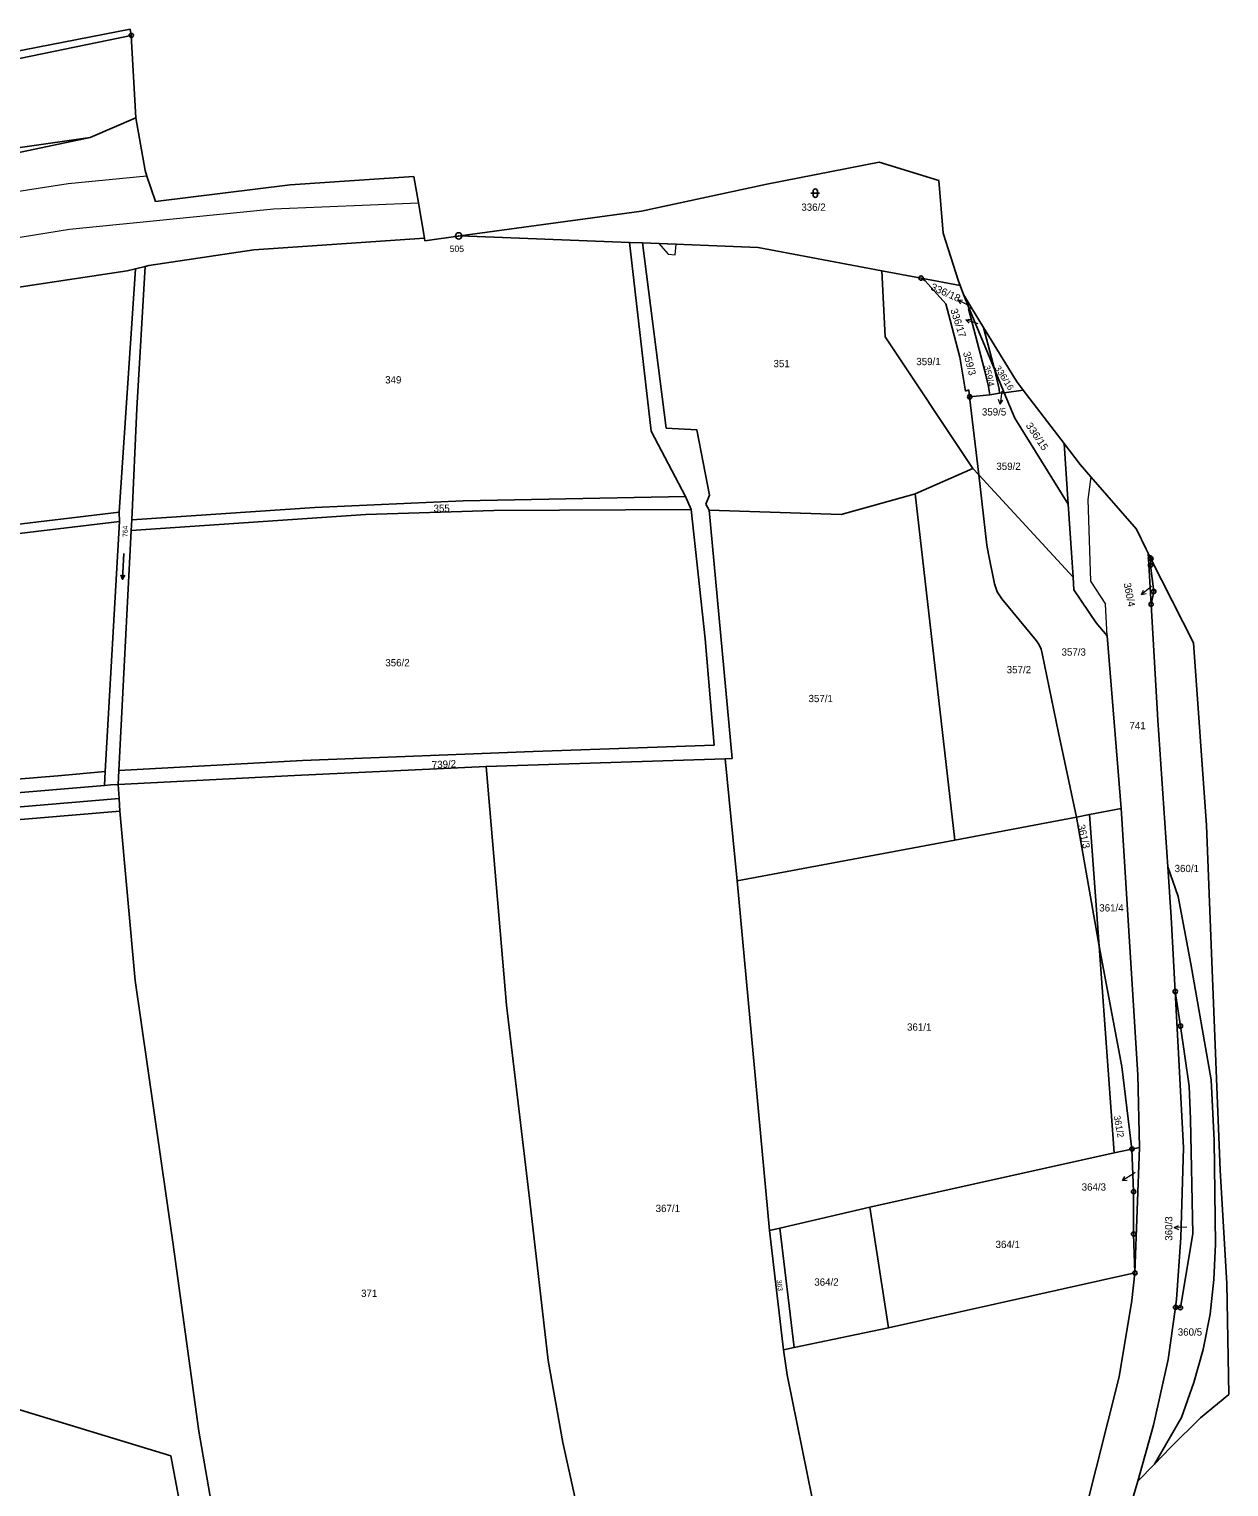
# Model space of a CAD drawing. Extents: x -701211 to -698780, y -1014269 to -1012378.
# Drawn here: x -699060.5 to -698780.2, y -1012938.4 to -1012597.8 of the extents above; entities that cross this region are included whole.
import ezdxf
from ezdxf.enums import TextEntityAlignment as Align

# ---------------------------------------------------------------- set-up
doc = ezdxf.new("R2010")
doc.units = 0
doc.header["$LTSCALE"] = 0.68
for name, color, linetype, lineweight in [('1', 7, 'Continuous', 25), ('13', 7, 'Continuous', 13), ('3', 7, 'Continuous', 25), ('4', 7, 'Continuous', 13), ('7', 7, 'Continuous', 13), ('8', 7, 'Continuous', 25)]:
    doc.layers.add(name, color=color, linetype=linetype, lineweight=lineweight)
doc.layers.add('2', color=7, linetype='Continuous')

msp = doc.modelspace()

# ---------------------------------------------------------------- linework, layer by layer
at = {"layer": '1'}
for p, q in [((-699126.02, -1012615.12), (-699036.85, -1012597.77)), ((-699036.85, -1012597.77), (-699036.63, -1012599.25)), ((-699081.26, -1012608.48), (-699036.63, -1012599.25)), ((-699036.63, -1012599.25), (-699035.57, -1012618.46)), ((-699046.25, -1012623.07), (-699035.57, -1012618.46)), ((-699035.57, -1012618.46), (-699033.39, -1012630.77)), ((-699046.25, -1012623.07), (-699081.97, -1012630.68)), ((-699046.25, -1012623.07), (-699072.26, -1012626.78)), ((-698888.11, -1012634.01), (-698861.89, -1012628.84)), ((-698861.89, -1012628.84), (-698847.93, -1012633.13)), ((-699033.39, -1012630.77), (-699032.95, -1012632.09)), ((-699032.95, -1012632.09), (-699030.95, -1012638.01)), ((-698999.49, -1012634.17), (-698970.61, -1012632.17)), ((-698969.55, -1012638.33), (-698970.61, -1012632.17)), ((-699030.95, -1012638.01), (-698999.49, -1012634.17)), ((-698917.43, -1012640.29), (-698888.11, -1012634.01)), ((-698847.93, -1012633.13), (-698846.97, -1012645.46)), ((-698968.12, -1012646.63), (-698969.55, -1012638.33)), ((-698843.38, -1012656.67), (-698846.97, -1012645.46)), ((-699032.52, -1012653), (-699008.02, -1012649.3)), ((-699008.02, -1012649.3), (-698968.12, -1012646.63)), ((-698968.02, -1012647.24), (-698968.12, -1012646.63)), ((-698959.75, -1012646.1), (-698920.25, -1012647.62)), ((-698920.25, -1012647.62), (-698917.16, -1012647.74)), ((-698915.17, -1012691.68), (-698920.25, -1012647.62)), ((-698917.16, -1012647.74), (-698890.19, -1012648.78)), ((-698911.66, -1012690.99), (-698917.16, -1012647.74)), ((-698890.19, -1012648.78), (-698861.31, -1012654.22)), ((-699092.82, -1012662.56), (-699037.6, -1012654.23)), ((-699039.44, -1012710.64), (-699035.62, -1012653.75)), ((-699037.6, -1012654.23), (-699035.62, -1012653.75)), ((-699035.62, -1012653.75), (-699033.39, -1012653.21)), ((-699035.36, -1012686.4), (-699033.39, -1012653.21)), ((-699033.39, -1012653.21), (-699032.52, -1012653)), ((-698861.31, -1012654.22), (-698852.1, -1012655.95)), ((-698860.52, -1012669.65), (-698861.31, -1012654.22)), ((-698852.1, -1012655.95), (-698851.13, -1012656.61)), ((-698852.1, -1012655.95), (-698843.01, -1012657.66)), ((-698851.13, -1012656.61), (-698846.34, -1012661.96)), ((-698843.38, -1012656.67), (-698843.01, -1012657.66)), ((-698843.01, -1012657.66), (-698842.23, -1012659.77)), ((-698846.34, -1012661.96), (-698845.32, -1012665.77)), ((-698842.23, -1012659.77), (-698840.32, -1012662.89)), ((-698840.87, -1012663.04), (-698842.23, -1012659.77)), ((-698840.87, -1012663.04), (-698840.32, -1012662.89)), ((-698834.96, -1012677.21), (-698840.87, -1012663.04)), ((-698840.32, -1012662.89), (-698837.52, -1012667.45)), ((-698845.32, -1012665.77), (-698843.08, -1012674.41)), ((-698839.98, -1012700.42), (-698860.52, -1012669.65)), ((-698834.96, -1012677.21), (-698837.52, -1012667.45)), ((-698837.52, -1012667.45), (-698829.82, -1012680.02)), ((-698843.08, -1012674.41), (-698841.72, -1012682.4)), ((-698832.67, -1012682.72), (-698834.96, -1012677.21)), ((-698829.82, -1012680.02), (-698828.22, -1012682.11)), ((-698841.72, -1012682.4), (-698840.95, -1012682.06)), ((-698840.95, -1012682.06), (-698840.76, -1012683.69)), ((-698836.05, -1012683.26), (-698840.76, -1012683.69)), ((-698836.05, -1012683.26), (-698833.75, -1012682.87)), ((-698833.75, -1012682.87), (-698832.67, -1012682.72)), ((-698832.67, -1012682.72), (-698828.22, -1012682.11)), ((-698830.2, -1012688.64), (-698832.67, -1012682.72)), ((-698818.69, -1012694.57), (-698828.22, -1012682.11)), ((-699036.52, -1012712.46), (-699035.36, -1012686.4)), ((-698840.76, -1012683.69), (-698838.64, -1012701.88)), ((-698830.2, -1012688.64), (-698817.74, -1012708.79)), ((-698915.17, -1012691.68), (-698907.14, -1012706.97)), ((-698911.66, -1012690.99), (-698904.48, -1012691.44)), ((-698904.48, -1012691.44), (-698901.52, -1012706.7)), ((-698814.91, -1012699.52), (-698818.69, -1012694.57)), ((-698818.69, -1012694.57), (-698817.74, -1012708.79)), ((-698853.48, -1012706.34), (-698839.98, -1012700.42)), ((-698839.98, -1012700.42), (-698838.64, -1012701.88)), ((-698812.44, -1012702.35), (-698814.91, -1012699.52)), ((-698838.64, -1012701.88), (-698816.6, -1012725.84)), ((-698838.64, -1012701.88), (-698836.72, -1012718.36)), ((-698801.76, -1012714.59), (-698812.44, -1012702.35)), ((-698907.14, -1012706.97), (-698959.08, -1012707.96)), ((-698907.14, -1012706.97), (-698905.81, -1012709.99)), ((-698901.52, -1012706.7), (-698902.42, -1012708.76)), ((-698870.75, -1012711.19), (-698853.7, -1012706.43)), ((-698853.7, -1012706.43), (-698853.48, -1012706.34)), ((-698844.23, -1012787.25), (-698853.48, -1012706.34)), ((-699039.44, -1012710.64), (-699104.93, -1012718.54)), ((-699039.4, -1012712.83), (-699039.44, -1012710.64)), ((-699036.52, -1012712.46), (-698993.76, -1012709.53)), ((-698993.76, -1012709.53), (-698959.08, -1012707.96)), ((-698951.92, -1012710.26), (-698981.79, -1012711.16)), ((-698905.81, -1012709.99), (-698951.92, -1012710.26)), ((-698905.81, -1012709.99), (-698902.58, -1012740.24)), ((-698902.42, -1012708.76), (-698901.65, -1012710.16)), ((-698901.65, -1012710.16), (-698870.75, -1012711.19)), ((-698896.26, -1012768.22), (-698901.65, -1012710.16)), ((-698817.74, -1012708.79), (-698816.6, -1012725.84)), ((-699039.4, -1012712.83), (-699113.18, -1012721.68)), ((-699039.4, -1012712.83), (-699042.73, -1012771.27)), ((-698981.79, -1012711.16), (-699036.63, -1012714.92)), ((-699036.63, -1012714.92), (-699036.52, -1012712.46)), ((-699036.63, -1012714.92), (-699039.53, -1012771.03)), ((-698799.5, -1012719.32), (-698801.76, -1012714.59)), ((-698836.72, -1012718.36), (-698836.39, -1012720.45)), ((-698836.39, -1012720.45), (-698834.96, -1012727.42)), ((-698799.5, -1012719.32), (-698799.05, -1012720.26)), ((-698798.53, -1012721.32), (-698799.05, -1012720.26)), ((-698798.36, -1012732.18), (-698799.05, -1012720.26)), ((-698798.42, -1012721.54), (-698798.54, -1012723.07)), ((-698798.54, -1012723.07), (-698797.74, -1012729.18)), ((-698798.53, -1012721.32), (-698798.42, -1012721.54)), ((-698798.42, -1012721.54), (-698788.46, -1012741.18)), ((-698834.96, -1012727.42), (-698834.33, -1012729.28)), ((-698816.6, -1012725.84), (-698816.4, -1012728.77)), ((-698834.33, -1012729.28), (-698833.28, -1012730.93)), ((-698833.28, -1012730.93), (-698825.18, -1012740.68)), ((-698816.4, -1012728.77), (-698811.18, -1012736.53)), ((-698797.74, -1012729.18), (-698798.36, -1012732.18)), ((-698796.81, -1012759.25), (-698798.36, -1012732.18)), ((-698811.18, -1012736.53), (-698808.65, -1012739.51)), ((-698900.42, -1012765.09), (-698902.58, -1012740.24)), ((-698825.18, -1012740.68), (-698824.54, -1012741.62)), ((-698805.36, -1012779.92), (-698808.65, -1012739.51)), ((-698785.46, -1012783.85), (-698788.46, -1012741.18)), ((-698824.54, -1012741.62), (-698824.08, -1012742.66)), ((-698824.08, -1012742.66), (-698823.8, -1012743.63)), ((-698823.8, -1012743.63), (-698820.02, -1012762.19)), ((-698794.47, -1012793.5), (-698796.81, -1012759.25)), ((-698942.76, -1012766.53), (-698900.42, -1012765.09)), ((-698820.02, -1012762.19), (-698815.81, -1012781.89)), ((-698996.59, -1012768.68), (-698942.76, -1012766.53)), ((-698953.68, -1012770.1), (-698897.88, -1012768.27)), ((-698897.88, -1012768.27), (-698896.26, -1012768.22)), ((-698895.06, -1012796.83), (-698897.88, -1012768.27)), ((-699042.73, -1012771.27), (-699053.75, -1012772.27)), ((-699039.53, -1012771.03), (-699039.7, -1012774.26)), ((-699039.53, -1012771.03), (-698996.59, -1012768.68)), ((-698998.45, -1012772.17), (-698953.68, -1012770.1)), ((-698948.95, -1012825.84), (-698953.68, -1012770.1)), ((-699090.43, -1012778.52), (-699042.9, -1012774.48)), ((-699053.75, -1012772.27), (-699084.52, -1012774.69)), ((-699041.4, -1012774.35), (-699039.7, -1012774.26)), ((-699039.7, -1012774.26), (-698998.45, -1012772.17)), ((-699039.47, -1012777.54), (-699039.7, -1012774.26)), ((-699093.38, -1012782.13), (-699039.47, -1012777.54)), ((-699039.26, -1012780.51), (-699039.47, -1012777.54)), ((-699094.95, -1012785.19), (-699039.26, -1012780.51)), ((-699039.26, -1012780.51), (-699035.71, -1012820.12)), ((-698815.81, -1012781.89), (-698844.23, -1012787.25)), ((-698812.78, -1012781.32), (-698815.81, -1012781.89)), ((-698815.81, -1012781.89), (-698810.53, -1012812.04)), ((-698805.36, -1012779.92), (-698812.78, -1012781.32)), ((-698812.78, -1012781.32), (-698810.53, -1012812.04)), ((-698801.47, -1012842.16), (-698805.36, -1012779.92)), ((-698784.24, -1012813.68), (-698785.46, -1012783.85)), ((-698844.23, -1012787.25), (-698895.06, -1012796.83)), ((-698794.47, -1012793.5), (-698793.66, -1012805.28)), ((-698794.47, -1012793.5), (-698792.08, -1012800.48)), ((-698887.52, -1012878.47), (-698895.06, -1012796.83)), ((-698792.08, -1012800.48), (-698789.1, -1012816.16)), ((-698792.72, -1012822.65), (-698793.66, -1012805.28)), ((-698810.53, -1012812.04), (-698807, -1012860.39)), ((-698789.1, -1012816.16), (-698784.31, -1012843.27)), ((-698784.24, -1012813.68), (-698782.27, -1012864.42)), ((-699035.71, -1012820.12), (-699026.91, -1012881.19)), ((-698792.72, -1012822.65), (-698791.5, -1012830.74)), ((-698791.78, -1012840.01), (-698792.72, -1012822.65)), ((-698943.52, -1012871.68), (-698948.95, -1012825.84)), ((-698790.8, -1012859.21), (-698791.78, -1012840.01)), ((-698801.09, -1012859.08), (-698801.47, -1012842.16)), ((-698784.31, -1012843.27), (-698783.65, -1012857.46)), ((-698789.18, -1012852.51), (-698788.59, -1012879.31)), ((-698807, -1012860.39), (-698864.05, -1012873.08)), ((-698802.86, -1012859.47), (-698807, -1012860.39)), ((-698801.09, -1012859.08), (-698802.86, -1012859.47)), ((-698802.86, -1012859.47), (-698802.46, -1012869.41)), ((-698802.16, -1012888.42), (-698801.09, -1012859.08)), ((-698791.42, -1012880.12), (-698790.8, -1012859.21)), ((-698783.65, -1012857.46), (-698783.32, -1012881.73)), ((-698782.27, -1012864.42), (-698780.68, -1012890.86)), ((-698802.46, -1012869.41), (-698802.47, -1012879.35)), ((-698939.21, -1012908.86), (-698943.52, -1012871.68)), ((-698885.12, -1012877.92), (-698864.05, -1012873.08)), ((-698864.05, -1012873.08), (-698859.75, -1012901.26)), ((-698887.52, -1012878.47), (-698885.12, -1012877.92)), ((-698884.24, -1012906.37), (-698887.52, -1012878.47)), ((-698885.12, -1012877.92), (-698881.79, -1012905.86)), ((-698802.47, -1012879.35), (-698802.16, -1012888.42)), ((-698792.41, -1012894.66), (-698791.42, -1012880.12)), ((-698788.59, -1012879.31), (-698791.52, -1012896.52)), ((-699026.91, -1012881.19), (-699020.81, -1012925.37)), ((-698783.32, -1012881.73), (-698783.72, -1012889.99)), ((-698802.16, -1012888.42), (-698859.75, -1012901.26)), ((-698802.91, -1012894.83), (-698802.16, -1012888.42)), ((-698783.72, -1012889.99), (-698784.55, -1012898.05)), ((-698780.68, -1012890.86), (-698780.21, -1012916.84)), ((-698792.66, -1012896.43), (-698792.41, -1012894.66)), ((-698805.87, -1012912.68), (-698802.91, -1012894.83)), ((-698794.39, -1012908.66), (-698792.66, -1012896.43)), ((-698791.52, -1012896.52), (-698792.66, -1012896.43)), ((-698784.55, -1012898.05), (-698786.23, -1012906.31)), ((-698859.75, -1012901.26), (-698881.79, -1012905.86)), ((-698881.79, -1012905.86), (-698884.24, -1012906.37)), ((-698883.39, -1012912.24), (-698884.24, -1012906.37)), ((-698786.23, -1012906.31), (-698788.39, -1012914)), ((-698935.8, -1012928.08), (-698939.21, -1012908.86)), ((-698797.8, -1012924), (-698794.39, -1012908.66)), ((-698877.56, -1012941.07), (-698883.39, -1012912.24)), ((-698813.84, -1012944.54), (-698805.87, -1012912.68)), ((-698788.39, -1012914), (-698791.24, -1012922.18)), ((-699027.41, -1012931.15), (-699079.02, -1012915.44)), ((-698780.21, -1012916.84), (-698786.86, -1012922.25)), ((-698801.49, -1012937.11), (-698797.8, -1012924)), ((-698791.24, -1012922.18), (-698797.57, -1012933.08)), ((-698786.86, -1012922.25), (-698793.8, -1012929.23)), ((-699020.81, -1012925.37), (-699002.81, -1013029.77)), ((-698927, -1012967.78), (-698935.8, -1012928.08)), ((-699020.23, -1012969.23), (-699027.41, -1012931.15)), ((-698797.57, -1012933.08), (-698793.8, -1012929.23)), ((-698801.49, -1012937.11), (-698797.57, -1012933.08)), ((-698801.49, -1012937.11), (-698806.08, -1012952.68))]:
    msp.add_line(p, q, dxfattribs=at)
for points in [[(-698917.43, -1012640.29), (-698959.75, -1012646.1), (-698968.02, -1012647.24)], [(-698840.87, -1012663.04), (-698841.06, -1012663.09), (-698837.31, -1012677.4), (-698836.39, -1012681.28), (-698836.19, -1012682.27), (-698836.05, -1012683.26)], [(-698834.96, -1012677.21), (-698834.09, -1012680.89), (-698833.9, -1012681.88), (-698833.75, -1012682.87)], [(-699042.73, -1012771.27), (-699042.9, -1012774.48), (-699041.4, -1012774.35)], [(-698810.53, -1012812.04), (-698805.17, -1012840.2), (-698802.86, -1012859.47)], [(-698791.5, -1012830.74), (-698789.45, -1012844.76), (-698789.18, -1012852.51)]]:
    msp.add_lwpolyline(points, dxfattribs=at)
at = {"layer": '13'}
msp.add_lwpolyline([(-698909.31, -1012648.04), (-698913.4, -1012647.89), (-698911.23, -1012650.34), (-698909.52, -1012650.48)], close=True, dxfattribs=at)
at = {"layer": '3'}
for p, q in [((-698877.331, -1012635.591), (-698877.331, -1012636.592)), ((-698876.329, -1012636.592), (-698876.329, -1012635.591)), ((-698877.831, -1012636.091), (-698875.829, -1012636.091)), ((-699038.646, -1012726.303), (-699039.096, -1012725.301))]:
    msp.add_line(p, q, dxfattribs=at)
msp.add_lwpolyline([(-699038.332, -1012720.311), (-699038.646, -1012726.303), (-699038.095, -1012725.353)], dxfattribs=at)
for centre, start, end in [((-698876.83, -1012635.5909), 0, 180), ((-698876.83, -1012636.5909), 180, 359.98789)]:
    msp.add_arc(centre, 0.5, start, end, dxfattribs=at)
at = {"layer": '4'}
for p, q in [((-699032.95, -1012632.09), (-699051.37, -1012633.91)), ((-699051.37, -1012633.91), (-699096.03, -1012640.88)), ((-699003.39, -1012639.75), (-698969.55, -1012638.33)), ((-699051.04, -1012644.52), (-699003.39, -1012639.75)), ((-699094.87, -1012651.53), (-699051.04, -1012644.52)), ((-698812.44, -1012702.35), (-698813.12, -1012707.71)), ((-698813.12, -1012707.71), (-698812.51, -1012726.79)), ((-698812.51, -1012726.79), (-698808.99, -1012732.16)), ((-698808.65, -1012739.51), (-698808.99, -1012732.16))]:
    msp.add_line(p, q, dxfattribs=at)
at = {"layer": '7'}
for p, q in [((-698843.56, -1012661.041), (-698842.911, -1012661.953)), ((-698841.654, -1012665.713), (-698840.856, -1012666.498)), ((-698833.616, -1012685.379), (-698832.997, -1012684.446)), ((-698800.612, -1012729.889), (-698799.519, -1012729.647)), ((-698805.055, -1012866.84), (-698803.94, -1012866.734)), ((-698792.989, -1012877.835), (-698791.971, -1012878.3))]:
    msp.add_line(p, q, dxfattribs=at)
for points in [[(-698840.91, -1012662.45), (-698843.56, -1012661.041), (-698842.44, -1012661.069)], [(-698838.8, -1012666.64), (-698841.654, -1012665.713), (-698840.547, -1012665.546)], [(-698833.25, -1012682.4), (-698833.616, -1012685.379), (-698833.991, -1012684.324)], [(-698798.28, -1012728), (-698800.612, -1012729.889), (-698800.149, -1012728.869)], [(-698802.08, -1012864.98), (-698802.51, -1012865.25), (-698805.055, -1012866.84), (-698804.471, -1012865.885)], [(-698789.99, -1012877.73), (-698792.989, -1012877.835), (-698792.006, -1012877.299)]]:
    msp.add_lwpolyline(points, dxfattribs=at)
at = {"layer": '8'}
for centre, radius in [((-699036.63, -1012599.2499), 0.5), ((-699036.63, -1012599.2499), 0.0303), ((-698960.13, -1012646.0898), 0.75), ((-698960.13, -1012646.0898), 0.03), ((-698852.1, -1012655.9499), 0.5), ((-698852.1, -1012655.9499), 0.0303), ((-698840.76, -1012683.6899), 0.5), ((-698840.76, -1012683.6899), 0.0303), ((-698798.53, -1012721.3199), 0.5), ((-698798.54, -1012723.0699), 0.5), ((-698798.42, -1012721.5399), 0.5), ((-698798.54, -1012723.0699), 0.0303), ((-698798.53, -1012721.3199), 0.0303), ((-698798.42, -1012721.5399), 0.0303), ((-698797.74, -1012729.1799), 0.5), ((-698797.74, -1012729.1799), 0.0303), ((-698798.36, -1012732.1799), 0.5), ((-698798.36, -1012732.1799), 0.0303), ((-698792.72, -1012822.6499), 0.5), ((-698792.72, -1012822.6499), 0.0303), ((-698791.5, -1012830.7399), 0.5), ((-698791.5, -1012830.7399), 0.0303), ((-698802.86, -1012859.4699), 0.5), ((-698802.86, -1012859.4699), 0.0303), ((-698802.46, -1012869.4099), 0.5), ((-698802.46, -1012869.4099), 0.0303), ((-698802.47, -1012879.3499), 0.5), ((-698802.47, -1012879.3499), 0.0303), ((-698802.16, -1012888.4199), 0.5), ((-698802.16, -1012888.4199), 0.0303), ((-698792.66, -1012896.4299), 0.5), ((-698792.66, -1012896.4299), 0.0303), ((-698791.52, -1012896.5199), 0.5), ((-698791.52, -1012896.5199), 0.0303)]:
    msp.add_circle(centre, radius, dxfattribs=at)

# ---------------------------------------------------------------- texts
at = {"layer": '2'}
for s, p in [('336/2', (-698880.08, -1012640.215)), ('741', (-698803.43, -1012761.375)), ('360/1', (-698792.88, -1012794.755))]:
    msp.add_text(s, height=1.7, dxfattribs=at).set_placement(p)
at = {"layer": '2', "width": 1.05}
msp.add_text('336/18', height=1.7, rotation=336, dxfattribs=at).set_placement((-698843.3805, -1012661.5746), align=Align.RIGHT)
at = {"layer": '2'}
msp.add_text('336/17', height=1.7, rotation=288, dxfattribs=at).set_placement((-698843.1368, -1012669.9977), align=Align.RIGHT)
for s, height, rotation, p in [('359/3', 1.7, 285, (-698842.33, -1012673.349)), ('359/4', 1.486, 283, (-698837.491, -1012676.543))]:
    msp.add_text(s, height=height, rotation=rotation, dxfattribs=at).set_placement(p)
for s, p in [('351', (-698884.689, -1012676.765)), ('359/1', (-698850.38, -1012676.285)), ('349', (-698975.419, -1012680.565)), ('359/2', (-698831.68, -1012700.765)), ('355', (-698964.109, -1012710.595)), ('357/3', (-698816.45, -1012744.165)), ('356/2', (-698974.42, -1012746.665)), ('357/2', (-698829.25, -1012748.285)), ('357/1', (-698875.56, -1012755.035)), ('361/4', (-698807.63, -1012803.955)), ('361/1', (-698852.54, -1012831.805)), ('364/3', (-698811.75, -1012869.185)), ('367/1', (-698911.27, -1012874.185)), ('364/1', (-698831.86, -1012882.595)), ('364/2', (-698874.21, -1012891.395)), ('371', (-698981.039, -1012894.025)), ('360/5', (-698789.29, -1012903.065))]:
    msp.add_text(s, height=1.7, dxfattribs=at).set_placement(p, align=Align.CENTER)
at = {"layer": '2', "width": 1.05}
msp.add_text('336/16', height=1.486, rotation=302, dxfattribs=at).set_placement((-698834.975, -1012676.936))
at = {"layer": '2'}
msp.add_text('359/5', height=1.7, dxfattribs=at).set_placement((-698832.21, -1012688.055), align=Align.RIGHT)
at = {"layer": '2', "width": 1.05}
msp.add_text('336/15', height=1.7, rotation=304, dxfattribs=at).set_placement((-698825.6984, -1012693.4087), align=Align.CENTER)
at = {"layer": '2'}
for s, height, rotation, p in [('764', 1.14, 90, (-699037.475, -1012715.13)), ('360/4', 1.7, 281, (-698804.2608, -1012730.0833)), ('739/2', 1.7, 3, (-698963.5245, -1012770.3824)), ('361/3', 1.7, 283, (-698814.8915, -1012786.6128)), ('361/2', 1.564, 281, (-698806.6484, -1012854.3403)), ('360/3', 1.7, 90, (-698793.405, -1012878.04)), ('363', 1.14, 277, (-698885.6981, -1012891.4))]:
    msp.add_text(s, height=height, rotation=rotation, dxfattribs=at).set_placement(p, align=Align.CENTER)
at = {"layer": '8'}
msp.add_text('505', height=1.5, dxfattribs=at).set_placement((-698958.889, -1012649.856), align=Align.RIGHT)

doc.saveas('drawing.dxf')
